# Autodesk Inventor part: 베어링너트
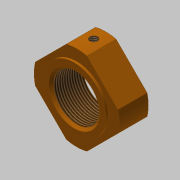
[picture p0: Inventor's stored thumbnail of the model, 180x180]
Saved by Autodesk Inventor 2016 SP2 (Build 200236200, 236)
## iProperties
Created: 2019-05
Part Number: 베어링너트
Material: 스테인리스강
Document SubType Name: Modeling
Designer: mduedu
Density: 1 g/cm^3
Appearance: 주황색
Author: mduedu
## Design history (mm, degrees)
sketch "스케치1"
  geometry: C1 r 17.5 at (0, 0); 1 further point
  constraints: 1 centre point, 1 coincident
  dimensions: "d0" = 35 diameter of C1
extrude "돌출1" new body sketch "스케치1" distance "d1" = 12; taper "d2" = 0 deg
sketch "스케치2"
  geometry: L1 (-21.213, 0)-(0, 21.213); L2 (0, 21.213)-(21.213, 0); L3 (21.213, 0)-(0, -21.213); L4 (0, -21.213)-(-21.213, 0); L5 (-21.213, 0)-(21.213, 0); L6 (0, 21.213)-(0, -21.213); 1 further point
  constraints: 12 end point, 2 midpoint, 2 parallel, 1 perpendicular, 1 vertical
  dimensions: "d3" = 30 distance of L1.end L2.end; "d5" = 30 distance of L2.end L3.end
extrude "돌출2" sketch "스케치2" stored distance "d6" = 12; taper "d7" = 0 deg
sketch "스케치3"
  geometry: C1 r 13 at (0, 0); 1 further point
  constraints: 1 centre point, 1 coincident
  dimensions: "d8" = 26 diameter of C1
extrude "돌출3" join sketch "스케치3" distance "d9" = 1; taper "d10" = 0 deg
hole "구멍1" diameter "d13" = 18.917; stored, may be unused: countersink angle "d17" = 90 deg, drill point angle "d19" = 118 deg; dims "d11" = 10, "d12" = 10, "d14" = 6, "d15" = 4, "d16" = 2, "d18" = 8
chamfer "모따기1" distance "d20" = 1; stored, may be unused: second distance "d21" = 2, angle "d22" = 45 deg
node "작업 평면1"
sketch "스케치5"
  geometry: L1 (-4.233, 0)-(4.233, 0) reference; 3 further points
  constraints: 1 midpoint, 1 vertical alignment
  dimensions: "d31" = 5 distance from line of point (0, 5) L1
hole "구멍3" sketch "스케치5" at (0, 5) diameter "d32" = 3.242; stored, may be unused: countersink angle "d36" = 90 deg, drill point angle "d38" = 118 deg; dims "d33" = 6, "d34" = 4, "d35" = 2, "d37" = 8
node "솔리드1"
